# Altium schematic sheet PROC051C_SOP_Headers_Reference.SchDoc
size 431 x 279 mm; Date: Not shown in title block; ApprovedBy: Not shown in title block; CheckedBy: Not shown in title block; Author: Not shown in title block; CompanyName: Not shown in title block; Engineer: Not shown in title block; Organization: Not shown in title block; Address1: Not shown in title block; Address2: Not shown in title block; Address3: Not shown in title block; Address4: Not shown in title block; DocumentNumber: 7; Revision: Use project parameter SCH_Rev; SheetNumber: 7; SheetTotal: 16; PageSetup: Record=PageOptions¦CenterHorizontal=True¦CenterVertical=True¦PrintScale=1.00¦XCorrection=1.00¦YCorrection=1.00¦PrintKind=0¦BorderSize=5000000¦LeftOffset=0¦BottomOffset=0¦Orientation=2¦PaperLength=1000¦PaperWidth=1000¦Scale=100¦PaperSource=15¦PrintQuality=600¦MediaType=1¦DitherType=10¦PaperKind=Letter¦PrintScaleMode=1
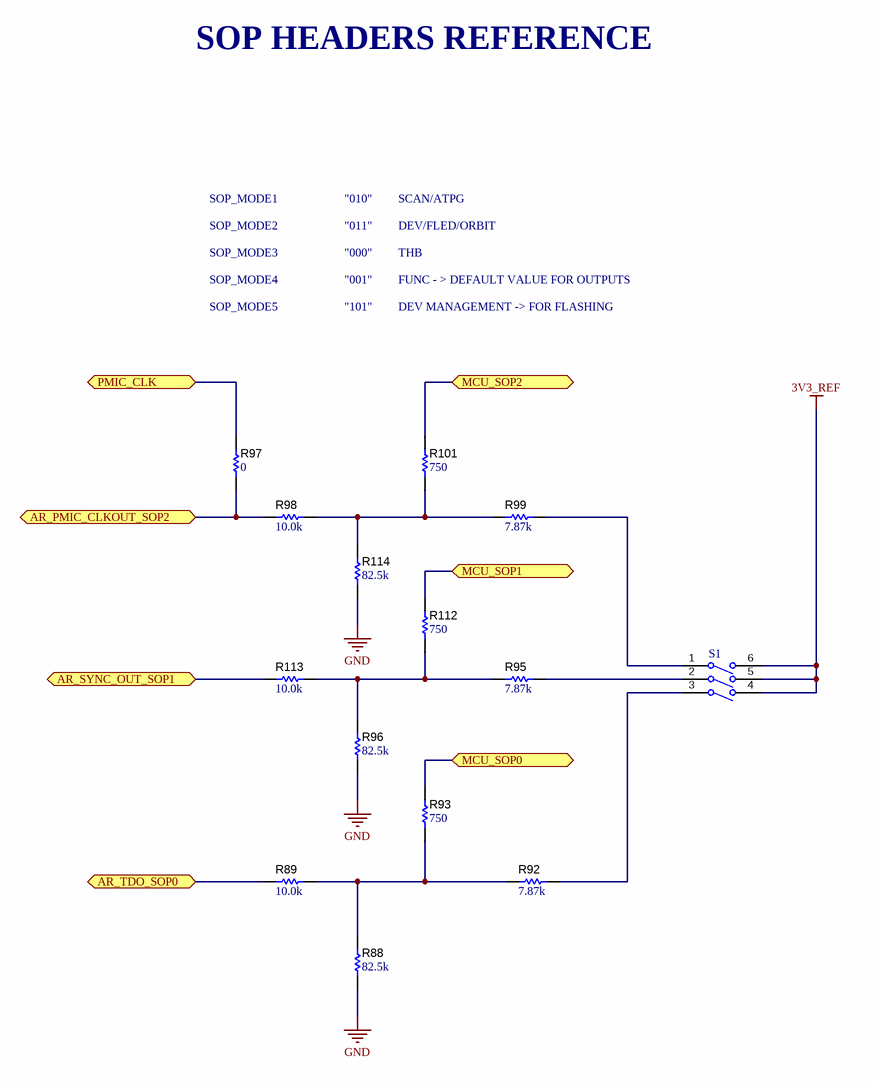
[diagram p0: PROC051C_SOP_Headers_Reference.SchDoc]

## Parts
R88  ValueDisplayed: 82.5k  [0402L]  (hidden comment: CRCW040282K5FKED)
R89  ValueDisplayed: 10.0k  [0402L]  (hidden comment: CRCW040210K0FKED)
R92  ValueDisplayed: 7.87k  [0402L]  (hidden comment: CRCW04027K87FKED)
R93  ValueDisplayed: 750  [0402L]  (hidden comment: CRCW0402750RFKED)
R95  ValueDisplayed: 7.87k  [0402L]  (hidden comment: CRCW04027K87FKED)
R96  ValueDisplayed: 82.5k  [0402L]  (hidden comment: CRCW040282K5FKED)
R97  ValueDisplayed: 0  [0402L]  (hidden comment: ERJ-2GE0R00X)
R98  ValueDisplayed: 10.0k  [0402L]  (hidden comment: CRCW040210K0FKED)
R99  ValueDisplayed: 7.87k  [0402L]  (hidden comment: CRCW04027K87FKED)
R101  ValueDisplayed: 750  [0402L]  (hidden comment: CRCW0402750RFKED)
R112  ValueDisplayed: 750  [0402L]  (hidden comment: CRCW0402750RFKED)
R113  ValueDisplayed: 10.0k  [0402L]  (hidden comment: CRCW040210K0FKED)
R114  ValueDisplayed: 82.5k  [0402L]  (hidden comment: CRCW040282K5FKED)
S1  219-3MST  [SW_219-3MST]  (value not drawn)

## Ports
AR_PMIC_CLKOUT_SOP2, AR_SYNC_OUT_SOP1, AR_TDO_SOP0, MCU_SOP0, MCU_SOP1, MCU_SOP2, PMIC_CLK

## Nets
3V3_REF: S1.4(B3) S1.5(B2) S1.6(B1)
GND: R88.1 R96.1 R114.1
AR_PMIC_CLKOUT_SOP2: R97.1 R98.1 ; port AR_PMIC_CLKOUT_SOP2
AR_SYNC_OUT_SOP1: R113.1 ; port AR_SYNC_OUT_SOP1
AR_TDO_SOP0: R89.1 ; port AR_TDO_SOP0
MCU_SOP0: R93.2 ; port MCU_SOP0
MCU_SOP1: R112.2 ; port MCU_SOP1
MCU_SOP2: R101.2 ; port MCU_SOP2
PMIC_CLK: R97.2 ; port PMIC_CLK
NetR88_2: R88.2 R89.2 R92.1 R93.1
NetR92_2: R92.2 S1.3(A3)
NetR95_1: R95.1 R96.2 R112.1 R113.2
NetR95_2: R95.2 S1.2(A2)
NetR98_2: R98.2 R99.1 R101.1 R114.2
NetR99_2: R99.2 S1.1(A1)

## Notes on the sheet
- SOP HEADERS REFERENCE
- SOP_MODE1
- "010"
- SCAN/ATPG
- SOP_MODE2
- SOP_MODE3
- "011"
- "000"
- DEV/FLED/ORBIT
- THB
- SOP_MODE4
- SOP_MODE5
- "001"
- "101"
- FUNC - > DEFAULT VALUE FOR OUTPUTS
- DEV MANAGEMENT -> FOR FLASHING

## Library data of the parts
R88 R96 R114 = CMP-0026574-2: RES, 82.5 k, 1%, 0.063 W, AEC-Q200 Grade 0, 0402; Manufacturer: Vishay-Dale; Power_W: 63mW; TempCo: 100 ppm/C; Value_Code: 82k5; Value: 82.5k; EIA_Code: E96; SizeX_mm: 1; SizeY_mm: 0.5; SizeZ_mm: 0.6; Value2: 0.063W; AEC Qualified: Y; VDC_V: 50V; AEC Grade: 0; AEC Category: Q200
R89 R98 R113 = CMP-0025958-3: RES, 10.0 k, 1%, 0.063 W, AEC-Q200 Grade 0, 0402; Manufacturer: Vishay-Dale; Power_W: 63mW; TempCo: 100 ppm/C; Value_Code: 10k0; Value: 10.0k; EIA_Code: E96; Res_ohm: 10k; SizeX_mm: 1; SizeY_mm: 0.5; SizeZ_mm: 0.6; Value2: 0.063W; AEC Qualified: Y; VDC_V: 50V; AEC Category: Q200; AEC Grade: 0
R92 R95 R99 = CMP-0026557-2: RES, 7.87 k, 1%, 0.063 W, AEC-Q200 Grade 0, 0402; Manufacturer: Vishay-Dale; Power_W: 63mW; TempCo: 100 ppm/C; Value_Code: 7k87; Value: 7.87k; EIA_Code: E96; SizeX_mm: 1; SizeY_mm: 0.5; SizeZ_mm: 0.6; Value2: 0.063W; AEC Qualified: Y; VDC_V: 50V; AEC Grade: 0; AEC Category: Q200
R93 R101 R112 = CMP-0026542-2: RES, 750, 1%, 0.063 W, AEC-Q200 Grade 0, 0402; Manufacturer: Vishay-Dale; Power_W: 63mW; TempCo: 100 ppm/C; Value_Code: 750R; Value: 750; EIA_Code: E96; SizeX_mm: 1; SizeY_mm: 0.5; SizeZ_mm: 0.6; Value2: 0.063W; AEC Qualified: Y; VDC_V: 50V; AEC Grade: 0; AEC Category: Q200
R97 = CMP-0026992-3: RES, 0, 5%, 0.1 W, AEC-Q200 Grade 0, 0402; Manufacturer: Panasonic; Power_W: 100mW; TempCo: 600 ppm/C; Value_Code: 0000; Value: 0; EIA_Code: E24; SizeX_mm: 1; SizeY_mm: 0.5; SizeZ_mm: 0.6; Value2: 0.1W; AEC Qualified: Y; VDC_V: 50V; AEC Category: Q200; SizeAreaWB_mm2: 3
S1 = CMP-0002269-1: Switch, SPST, Slide, Off-On, 3 Pos, 0.1A, 20V, SMD; Manufacturer: CTS Electrocomponents; CurrentRating_mA: 100A; PositionCount: 3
